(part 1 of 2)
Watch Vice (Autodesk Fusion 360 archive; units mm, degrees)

design "Watch Vice" references "WatchCase V3"
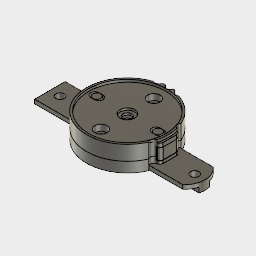
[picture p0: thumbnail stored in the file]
parameter "d90" = 4
parameter "d106" = 4
component_insert "Component Insert"
sketch "Sketch1"
  line L1 (0, 20.2285) -> (0, 20.1)
  line L2 (0, 20.95) -> (0, 20.2285)
  arc A1 centre (0, 0) radius 20.1 clockwise from (19.4682, -5) to (-3.612, 19.7728)
  arc A2 centre (19.1697, -3.3264) radius 1.7 clockwise from (20.869, -3.3751) to (19.4682, -5)
  arc A3 centre (-96.8326, 0) radius 117.75 clockwise from (20.869, 3.3751) to (20.869, -3.3751)
  arc A4 centre (19.1697, 3.3264) radius 1.7 clockwise from (19.4682, 5) to (20.869, 3.3751)
  arc A5 centre (0, 0) radius 20.1 clockwise from (3.612, 19.7728) to (19.4682, 5)
  arc A6 centre (2.1023, 18.9913) radius 1.7 clockwise from (0.8, 20.0841) to (3.612, 19.7728)
  arc A7 centre (0, 0) radius 20.1 clockwise from (-0.8, 20.0841) to (0.8, 20.0841)
  arc A8 centre (-2.1023, 18.9913) radius 1.7 clockwise from (-3.612, 19.7728) to (-0.8, 20.0841)
  arc A9 centre (0, 0) radius 21.6 clockwise from (-17.2241, -13.0342) to (-17.2241, 13.0342)
  arc A10 centre (-18.5, 13.9997) radius 1.6 clockwise from (-16.9962, 14.5462) to (-17.2241, 13.0342)
  arc A11 centre (-15.2104, 15.1952) radius 1.9 clockwise from (-16.9962, 14.5462) to (-14.5633, 16.9815)
  arc A12 centre (-14.0183, 18.4859) radius 1.6 clockwise from (-13.0515, 17.211) to (-14.5633, 16.9815)
  arc A13 centre (0, 0) radius 21.6 clockwise from (-13.0515, 17.211) to (13.0515, 17.211)
  arc A14 centre (14.0183, 18.4859) radius 1.6 clockwise from (14.5633, 16.9815) to (13.0515, 17.211)
  arc A15 centre (15.2104, 15.1952) radius 1.9 clockwise from (14.5633, 16.9815) to (16.9962, 14.5462)
  arc A16 centre (18.5, 13.9997) radius 1.6 clockwise from (17.2241, 13.0342) to (16.9962, 14.5462)
  arc A17 centre (0, 0) radius 21.6 clockwise from (17.2241, 13.0342) to (17.2241, -13.0342)
  arc A18 centre (18.5, -13.9997) radius 1.6 clockwise from (16.9962, -14.5462) to (17.2241, -13.0342)
  arc A19 centre (15.2104, -15.1952) radius 1.9 clockwise from (16.9962, -14.5462) to (14.5633, -16.9815)
  arc A20 centre (14.0183, -18.4859) radius 1.6 clockwise from (13.0515, -17.211) to (14.5633, -16.9815)
  arc A21 centre (0, 0) radius 21.6 clockwise from (13.0515, -17.211) to (-13.0515, -17.211)
  arc A22 centre (-14.0183, -18.4859) radius 1.6 clockwise from (-14.5633, -16.9815) to (-13.0515, -17.211)
  arc A23 centre (-15.2104, -15.1952) radius 1.9 clockwise from (-14.5633, -16.9815) to (-16.9962, -14.5462)
  arc A24 centre (-18.5, -13.9997) radius 1.6 clockwise from (-17.2241, -13.0342) to (-16.9962, -14.5462)
  circle C1 centre (15.2104, 15.1952) radius 0.625
  circle C2 centre (-15.2104, 15.1952) radius 0.625
  circle C3 centre (15.2104, -15.1952) radius 0.625
  circle C4 centre (-15.2104, -15.1952) radius 0.625
  circle C5 centre (5.1662, 20.5772) radius 1.75
  circle C6 centre (-5.1662, 20.5772) radius 1.75
  circle C7 centre (19.7754, 6.7228) radius 1.75
  circle C8 centre (19.7754, -6.7228) radius 1.75
  circle C9 centre (0, 20.1) radius 0.9
  circle C10 centre (0, 20.95) radius 1.75
  arc A25 centre (0, 0) radius 20.1 clockwise from (19.4682, 5) to (19.4682, -5)
  dimension "d6" diameter C8 = 3.5
  dimension "d7" diameter C9 = 1.8
  dimension "d8" diameter C10 = 3.5
extrude "Extrude1" new body sketch "Sketch1" profile of A1 A2 A3 A4 A5 A6 A7 A8 C5 C6 C7 C8 C10 blind 10
extrude "Extrude2" cut sketch "Sketch1" profile of A6 A7 A8 C10 no distance stored
extrude "Extrude3" sketch "Sketch1" profile of A2 A3 A4 A25 blind -1.1
offset_faces "OffsetFaces1" distance -0.1
sketch "Sketch2" plane through (0, 0, 0) normal (1, 0, 0) x axis (0, 1, 0)
  line L1 (-20, 10) -> (19.1, 10)
  line L2 (0, 3) -> (0, 0)
  line L3 (20, 3) -> (-20, 3)
  line L4 (0, 10) -> (0, 3)
  line L5 (-20, 3) -> (-20, 10)
  line L6 (-16, 6) -> (-16, 10)
  line L7 (-14.55, 6) -> (-16, 6)
  line L8 (-14.55, 3) -> (-14.55, 6)
  line L9 (-11.45, 6) -> (-11.45, 3)
  line L10 (-10, 6) -> (-11.45, 6)
  line L11 (-10, 10) -> (-10, 6)
  line L12 (11.45, 6) -> (11.45, 3)
  line L13 (10, 6) -> (11.45, 6)
  line L14 (10, 10) -> (10, 6)
  line L15 (-11.45, 6) -> (-14.55, 6)
  line L16 (-13, 10) -> (-13, 6)
  line L17 (-13, 3) -> (-13, 6)
  line L18 (13, 10) -> (13, 6)
  line L19 (13, 3) -> (13, 6)
  line L20 (-20, 0) -> (19.0241, 0)
  line L21 (-14.25, 0) -> (-14.25, 3)
  line L22 (-13, 0) -> (-13, 3)
  line L23 (-11.75, 0) -> (-11.75, 3)
  line L24 (-11.75, 3) -> (-14.25, 3)
  line L25 (13, 0) -> (13, 3)
  line L26 (11.75, 0) -> (11.75, 3)
  point P10 (-16, 10)
  point P11 (-16, 6)
  point P1 (0, 0)
  dimension "d19" distance P10 P11 = 4
  dimension "d20" distance L8 L9 = 3.1
  dimension "d22" distance L4 L11 = 10
  dimension "d23" distance L6 L11 = 6
  dimension "d24" distance P1 L3 = 3
  dimension "d27" distance L21 L23 = 2.5
  dimension "d28" distance L7 L20 = 6
revolve "Revolve1" sketch "Sketch2" AlongAngle 360
revolve "Revolve2" sketch "Sketch2" AlongAngle 360
work_plane "WorkPlane1" AlongDistance 3
split "Split1" bodies "Clamp Upper"
sketch "Sketch4" plane through (0, 0, 0) normal (0, 1, 0) x axis (1, 0, 0)
  line L1 (-20, 0) -> (20.8174, 0)
  line L2 (20.8174, 4) -> (20.8174, 0)
  line L3 (-20, 4) -> (20.8174, 4)
  line L4 (-20, 0) -> (-20, 4)
  point P4 (20.8174, 0)
  point P5 (20.8174, 4)
  dimension "d41" distance P4 P5 = 4
extrude "Extrude5" add sketch "Sketch4" distance 5.2
delete_face "DeleteFace1"
sketch "Sketch7" plane through (0, 0, 0) normal (0, 0, -1) x axis (1, 0, 0)
  line L1 (20.7887, 2.6) -> (-19.8303, 2.6)
  line L2 (38, 7.5) -> (-38, 7.5)
  line L3 (38, -7.5) -> (38, 7.5)
  line L4 (-38, -7.5) -> (38, -7.5)
  line L5 (-38, 7.5) -> (-38, -7.5)
  line L6 (-19.8303, -2.6) -> (20.7887, -2.6)
  line L7 (-20, 0) -> (-38, 0)
  line L8 (-34.6144, -7.5) -> (-34.6144, 7.5)
  line L9 (0, 7.5) -> (0, 0)
  line L10 (-38, 2.6) -> (-19.8303, 2.6)
  line L11 (-38, -2.6) -> (-19.8303, -2.6)
  line L12 (38, 2.6) -> (20.7887, 2.6)
  line L13 (38, -2.6) -> (20.7887, -2.6)
  arc A1 centre (-96.8326, 0) radius 117.65 clockwise from (20.7691, 3.3723) to (20.7887, 2.6)
  arc A2 centre (19.1697, 3.3264) radius 1.6 clockwise from (19.4506, 4.9016) to (20.7691, 3.3723)
  arc A3 centre (19.7754, 6.7228) radius 1.85 clockwise from (19.4506, 4.9016) to (18.365, 7.92)
  arc A4 centre (0, 0) radius 20 clockwise from (-19.8303, 2.6) to (18.365, 7.92)
  circle C1 centre (0, 13) radius 1.25
  arc A5 centre (0, 0) radius 20 clockwise from (-19.8303, -2.6) to (-19.8303, 2.6)
  circle C2 centre (-33, 0) radius 2.025
  arc A6 centre (-28, 0) radius 10 clockwise from (-34.6144, -7.5) to (-34.6144, 7.5)
  arc A7 centre (28, 0) radius 10 clockwise from (34.6144, 7.5) to (34.6144, -7.5)
  circle C3 centre (33, 0) radius 2.025
  arc A8 centre (5.1662, -20.5772) radius 1.85 clockwise from (3.5232, -19.7268) to (6.1713, -19.0241)
  arc A9 centre (0, 0) radius 20 clockwise from (18.365, -7.92) to (6.1713, -19.0241)
  arc A10 centre (19.7754, -6.7228) radius 1.85 clockwise from (18.365, -7.92) to (19.4506, -4.9016)
  arc A11 centre (19.1697, -3.3264) radius 1.6 clockwise from (20.7691, -3.3723) to (19.4506, -4.9016)
  arc A12 centre (-96.8326, 0) radius 117.65 clockwise from (20.7691, 3.3723) to (20.7691, -3.3723)
  arc A13 centre (19.1697, 3.3264) radius 1.6 clockwise from (19.4506, 4.9016) to (20.7691, 3.3723)
  arc A14 centre (19.7754, 6.7228) radius 1.85 clockwise from (19.4506, 4.9016) to (18.365, 7.92)
  arc A15 centre (0, 0) radius 20 clockwise from (-6.1713, -19.0241) to (18.365, 7.92)
  arc A16 centre (-5.1662, -20.5772) radius 1.85 clockwise from (-6.1713, -19.0241) to (-3.5232, -19.7268)
  arc A17 centre (-2.1023, -18.9913) radius 1.6 clockwise from (-1.8093, -20.5643) to (-3.5232, -19.7268)
  arc A18 centre (0, -20.95) radius 1.85 clockwise from (-1.8093, -20.5643) to (1.8093, -20.5643)
  arc A19 centre (2.1023, -18.9913) radius 1.6 clockwise from (3.5232, -19.7268) to (1.8093, -20.5643)
  circle C4 centre (0, 13) radius 1.55
  circle C5 centre (0, -13) radius 1.55
  point P12 (-38, 7.5)
  point P15 (-38, -7.5)
  point P1 (0, 0)
  point P23 (-33, 0)
  dimension "d73" distance P12 P15 = 15
  dimension "d74" distance P1 P23 = 33
  dimension "d76" radius A6 = 10
  dimension "d77" distance L5 P23 = 5
  dimension "d78" diameter C2 = 4.05
  dimension "d138" distance L10 L11 = 5.2
extrude "Extrude14" add sketch "Sketch7" profile of L1 A1 A2 A3 A4 L2 L4 L5 L6 A5 C2 A6 A7 C3 L10 L11 L12 L13 A8 A9 A10 A11 A12 A13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 along normal blind 2
offset_faces "OffsetFaces3" distance 2
extrude "Extrude15" add sketch "Sketch7" profile of L1 L6 A5 C2 A6 A7 C3 L10 L11 L12 L13 A12 A15 along normal blind 4.5
sketch "Sketch3" plane through (0, 0, 0) normal (0, 1, 0) x axis (1, 0, 0)
  line L1 (20, -10) -> (-20, -10)
  line L2 (0, -7) -> (0, 0)
  line L3 (3.6, -8) -> (3.6, -10)
  line L4 (2.1, -8) -> (3.6, -8)
  line L5 (2.1, -7) -> (2.1, -8)
  line L6 (0, -7) -> (2.1, -7)
  line L7 (0, -10) -> (0, -7)
  line L8 (3.6, -10) -> (0, -10)
  line L9 (20.8174, -3) -> (-20, -3)
  line L10 (-22, -7) -> (22, -7)
  line L11 (-22, -1.4022) -> (-22, -7)
  line L12 (22, -1.4022) -> (-22, -1.4022)
  line L13 (22, -7) -> (22, -1.4022)
  point P5 (3.6, -10)
  point P10 (0, -10)
  point P6 (3.6, -8)
  point P3 (20, -10)
  point P2 (-20, -10)
  point P8 (2.1, -7)
  dimension "d29" distance L5 L7 = 2.1
  dimension "d30" distance P5 P10 = 3.6
  dimension "d31" distance P5 P6 = 2
  dimension "d34" = 1
  dimension "d35" distance P3 L13 = 2
  dimension "d36" distance P2 L11 = 2
  dimension "d136" distance P5 P8 = 3
revolve "Revolve3" sketch "Sketch3" AlongAngle 360
extrude "Extrude4" cut sketch "Sketch3" profile of L6 L10 L11 L12 L13 distance 10
extrude "Extrude6" new body of existing geometry blind 5.6 bodies "Clamp Jaw 1"
offset_faces "OffsetFaces2" distance -0.15
sketch "Sketch5" plane through (0, 0, 0) normal (0, 1, 0) x axis (1, 0, 0)
  line L1 (20.8174, -7.0022) -> (-20, -7.0022)
  line L2 (-20, -1.5522) -> (20.8174, -1.5522)
  line L3 (6.8325, -1.5522) -> (4.8489, -7.0022)
  line L4 (0, -1.5522) -> (0, 0)
  line L5 (0, -7.0022) -> (0, -1.5522)
  line L6 (6.6197, -1.5522) -> (4.636, -7.0022)
  line L7 (0, -6.0022) -> (5, -6.0022)
  line L8 (-6.8325, -1.5522) -> (-4.8489, -7.0022)
  line L9 (-6.6197, -1.5522) -> (-4.636, -7.0022)
  line L10 (0, -6.0022) -> (-5, -6.0022)
  point P13 (5, -6.0022)
  point P14 (0, -6.0022)
  dimension "d47" distance L3 L6 = 0.2
  dimension "d48" angle L2 L6 = 70
  dimension "d49" distance P13 P14 = 5
  dimension "d50" distance L1 L7 = 1
extrude "Extrude7" cut sketch "Sketch5" profile of L1 L2 L3 L5 L6 L7 L8 L9 L10 distance 10 bodies "Clamp Jaw Center", "Clamp Jaws 2"
sketch "Sketch6" plane through (0, 0, 7.0022) normal (0, 0, 1) x axis (-1, 0, 0)
  line L1 (-4.8489, 4.85) -> (-4.8489, -4.85)
  line L2 (-19.0736, 4.85) -> (-4.8489, 4.85)
  line L3 (-4.8489, -4.85) -> (-19.0736, -4.85)
  line L4 (14, -2) -> (16, -2)
  line L5 (16, 2) -> (14, 2)
  line L6 (6.6197, -4.85) -> (-6.6197, -4.85)
  line L7 (0, -4.85) -> (0, 0)
  line L8 (0, 0) -> (14, 0)
  line L9 (16, 0) -> (14, 0)
  line L10 (-14, -2) -> (-16, -2)
  line L11 (-16, 2) -> (-14, 2)
  line L12 (1.7, -4) -> (1.7, -5.95)
  line L13 (-1.7, -4) -> (1.7, -4)
  line L14 (-1.7, -5.95) -> (-1.7, -4)
  line L15 (-1.9, -3.8) -> (1.9, -3.8)
  line L16 (-1.9, -5.95) -> (-1.9, -3.8)
  line L17 (1.9, -3.8) -> (1.9, -5.95)
  line L18 (1.7, 4) -> (1.7, 5.95)
  line L19 (1.9, 3.8) -> (1.9, 5.95)
  line L20 (-1.9, 5.95) -> (-1.9, 3.8)
  line L21 (-1.7, 5.95) -> (-1.7, 4)
  line L22 (-1.7, 4) -> (1.7, 4)
  line L23 (-1.9, 3.8) -> (1.9, 3.8)
  arc A1 centre (-19.174, 3.1734) radius 1.6 clockwise from (-20.7734, 3.2172) to (-19.4413, 4.7509)
  arc A2 centre (96.8326, 0) radius 117.65 clockwise from (-20.7734, -3.2172) to (-20.7734, 3.2172)
  arc A3 centre (-19.174, -3.1734) radius 1.6 clockwise from (-19.4413, -4.7509) to (-20.7734, -3.2172)
  arc A4 centre (14, 0) radius 2 clockwise from (14, -2) to (14, 2)
  arc A5 centre (16, 0) radius 2 clockwise from (16, 2) to (16, -2)
  circle C1 centre (15, 0) radius 1.95
  arc A6 centre (-14, 0) radius 2 clockwise from (-14, 2) to (-14, -2)
  arc A7 centre (-16, 0) radius 2 clockwise from (-16, -2) to (-16, 2)
  circle C2 centre (-15, 0) radius 1.95
  circle C3 centre (0, 0) radius 1.75
  arc A8 centre (0, -5.95) radius 1.7 clockwise from (1.7, -5.95) to (-1.7, -5.95)
  arc A9 centre (0, -5.95) radius 1.9 clockwise from (1.9, -5.95) to (-1.9, -5.95)
  arc A10 centre (0, 5.95) radius 1.7 clockwise from (-1.7, 5.95) to (1.7, 5.95)
  arc A11 centre (0, 5.95) radius 1.9 clockwise from (-1.9, 5.95) to (1.9, 5.95)
  arc A12 centre (-19.7754, 6.7228) radius 2 clockwise from (-19.0736, 4.85) to (-19.4413, 4.7509)
  arc A13 centre (-19.7754, -6.7228) radius 2 clockwise from (-19.4413, -4.7509) to (-19.0736, -4.85)
  point P13 (14, -2)
  point P16 (16, -2)
  point P1 (0, 0)
  point P21 (15, 0)
  point P32 (1.7, -5.95)
  dimension "d53" diameter A5 = 4
  dimension "d54" diameter C1 = 3.9 (= "d53 - 0.1 mm")
  dimension "d55" distance P13 P16 = 2
  dimension "d56" distance P1 P21 = 15
  dimension "d61" diameter C3 = 3.5
  dimension "d63" radius A8 = 1.7 (= "( 3.6 / 2 ) * 1 mm - 0.1 mm")
  dimension "d64" distance L6 P32 = 1.1
  dimension "d65" distance L8 L13 = 4
  dimension "d66" = 0.2
extrude "Extrude8" add sketch "Sketch6" profile of C1 C2 along normal blind 2
extrude "Extrude9" cut sketch "Sketch6" profile of A5 A4 L4 L5 C1 A6 L10 A7 C2 L11 along normal blind 7 and against normal blind 1
extrude "Extrude13" cut sketch "Sketch6" profile of C3 no distance stored
extrude "Extrude11" sketch "Sketch6" profile of L6 A8 L12 L14 A10 L18 L21 L22 to an object
extrude "Extrude16" cut sketch "Sketch6" profile of L6 A8 L12 L13 L14 L16 L15 L17 A9 A10 A11 L18 L19 L20 L21 L22 L23 to an object
sketch "Sketch13" plane through (0, 0, 10) normal (0, 0, 1) x axis (-1, 0, 0)
  circle C1 centre (0, 0) radius 19
  dimension "d133" diameter C1 = 38
extrude "Extrude21" cut sketch "Sketch13" against normal blind 1
extrude "Extrude22" add of existing geometry blind 0.2
sketch "Sketch8" plane through (0, 0, 0) normal (0, 0, 1) x axis (-1, 0, 0)
  line L1 (38, -7.5) -> (18.5405, -7.5)
  line L2 (38, 7.5) -> (38, -7.5)
  line L3 (18.5405, 7.5) -> (38, 7.5)
  line L4 (27, -7.5) -> (27, -13.5)
  line L5 (25, -7.5) -> (27, -7.5)
  line L6 (25, -13.5) -> (25, -7.5)
  line L7 (27, -13.5) -> (25, -13.5)
  line L8 (33, 0) -> (0, 0)
  line L9 (0, -19.1) -> (0, 0)
  line L10 (38, -7.5) -> (18.5405, -7.5)
  line L11 (38, 7.5) -> (38, -7.5)
  line L12 (18.5405, 7.5) -> (38, 7.5)
  line L13 (-18.0966, -7.5) -> (-34.6144, -7.5)
  line L14 (-34.6144, 7.5) -> (-18.0966, 7.5)
  line L15 (-25, -13.5) -> (-25, -7.5)
  line L16 (-27, -13.5) -> (-25, -13.5)
  line L17 (-27, -7.5) -> (-27, -13.5)
  line L18 (-25, -7.5) -> (-27, -7.5)
  line L19 (27, 7.5) -> (27, 13.5)
  line L20 (27, 13.5) -> (25, 13.5)
  line L21 (25, 13.5) -> (25, 7.5)
  line L22 (25, 7.5) -> (27, 7.5)
  line L23 (-27, 13.5) -> (-25, 13.5)
  line L24 (-27, 7.5) -> (-27, 13.5)
  line L25 (-25, 13.5) -> (-25, 7.5)
  line L26 (-25, 7.5) -> (-27, 7.5)
  line L27 (42.5, -12) -> (21.36, -12)
  line L28 (42.5, 3) -> (42.5, -12)
  line L29 (24.3156, 3) -> (42.5, 3)
  line L30 (-36.1394, 12) -> (-21.36, 12)
  line L31 (-21.36, -12) -> (-36.1394, -12)
  line L32 (38, -7.5) -> (18.5405, -7.5)
  line L33 (38, 7.5) -> (38, -7.5)
  line L34 (18.5405, 7.5) -> (38, 7.5)
  circle C1 centre (33, 0) radius 2.025
  arc A1 centre (0, 0) radius 20 clockwise from (18.5405, 7.5) to (18.5405, -7.5)
  arc A2 centre (0, -20.95) radius 1.85 clockwise from (-1.8093, -20.5643) to (1.8093, -20.5643)
  arc A3 centre (0, 0) radius 20 clockwise from (-18.365, 7.92) to (19.3649, 5)
  arc A4 centre (0, 0) radius 20 clockwise from (19.3649, -5) to (6.1713, -19.0241)
  arc A5 centre (5.1662, -20.5772) radius 1.85 clockwise from (3.5232, -19.7268) to (6.1713, -19.0241)
  arc A6 centre (2.1023, -18.9913) radius 1.6 clockwise from (3.5232, -19.7268) to (1.8093, -20.5643)
  arc A7 centre (0, -20.95) radius 1.85 clockwise from (-1.8093, -20.5643) to (1.8093, -20.5643)
  arc A8 centre (-2.1023, -18.9913) radius 1.6 clockwise from (-1.8093, -20.5643) to (-3.5232, -19.7268)
  arc A9 centre (-5.1662, -20.5772) radius 1.85 clockwise from (-6.1713, -19.0241) to (-3.5232, -19.7268)
  arc A10 centre (0, 0) radius 20 clockwise from (-6.1713, -19.0241) to (-18.365, -7.92)
  arc A11 centre (-28, 0) radius 10 clockwise from (-34.6144, -7.5) to (-34.6144, 7.5)
  arc A12 centre (0, 0) radius 24.5 clockwise from (-7.5598, -23.3045) to (-21.36, -12)
  arc A13 centre (-6.1713, -19.0241) radius 4.5 clockwise from (-5.6365, -23.4922) to (-7.5598, -23.3045)
  arc A14 centre (-2.1023, -18.9913) radius 5.7226 clockwise from (-1.0546, -24.6172) to (-5.6365, -23.4922)
  arc A15 centre (-1.8093, -20.5643) radius 4.1226 clockwise from (-0.001, -24.2691) to (-1.0546, -24.6172)
  arc A16 centre (1.8093, -20.5643) radius 4.1235 clockwise from (1.0544, -24.6181) to (-0.001, -24.2691)
  arc A17 centre (2.1023, -18.9913) radius 5.7235 clockwise from (5.6377, -23.4923) to (1.0544, -24.6181)
  arc A18 centre (6.1713, -19.0241) radius 4.5 clockwise from (7.5598, -23.3045) to (5.6377, -23.4923)
  arc A19 centre (0, 0) radius 24.5 clockwise from (21.36, -12) to (7.5598, -23.3045)
  arc A20 centre (-28, 0) radius 14.5 clockwise from (-36.1394, -12) to (-36.1394, 12)
  arc A21 centre (0, 0) radius 24.5 clockwise from (-21.36, 12) to (24.3156, 3)
  circle C2 centre (33, 0) radius 2.025
  arc A22 centre (0, 0) radius 20 clockwise from (18.5405, 7.5) to (18.5405, -7.5)
  point P8 (27, -13.5)
  point P11 (25, -13.5)
  point P10 (25, -7.5)
  dimension "d86" distance P8 P11 = 2
  dimension "d88" distance P10 P11 = 6
  dimension "d89" distance L6 L9 = 25
  dimension "d96" distance L2 L28 = 4.5
  dimension "d97" distance L1 L27 = 4.5 (= "d96")
  dimension "d98" distance L3 L29 = 4.5 (= "d96")
  dimension "d99" distance A3 A21 = 4.5 (= "d96")
  dimension "d100" distance A4 A19 = 4.5 (= "d96")
  dimension "d101" distance A10 A12 = 4.5 (= "d96")
  dimension "d102" distance L13 L31 = 4.5 (= "d96")
  dimension "d103" distance A11 A20 = 4.5 (= "d96")
  dimension "d104" distance L14 L30 = 4.5 (= "d96")
extrude "Extrude17" add sketch "Sketch8" profile of L4 L5 L6 L7 L10 L12 L13 L14 L15 L16 L17 L18 L19 L20 L21 L22 L23 L24 L25 L26 L27 L30 L31 L32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 against normal blind 1.5
mesh "Mesh2"
sketch "Sketch9" plane through (0, 0, 10.2) normal (0, 0, 1) x axis (-1, 0, 0)
  line L1 (18.1981, -17.1374) -> (17.1374, -18.1981)
  line L2 (14.6625, -13.6019) -> (18.1981, -17.1374)
  line L3 (13.6019, -14.6625) -> (14.6625, -13.6019)
  line L4 (17.1374, -18.1981) -> (13.6019, -14.6625)
  line L5 (0, -13) -> (0, 0)
  line L6 (0, 0) -> (14, 0)
  line L7 (0, 0) -> (14.1322, -14.1322)
  line L8 (-17.1374, -18.1981) -> (-13.6019, -14.6625)
  line L9 (-13.6019, -14.6625) -> (-14.6625, -13.6019)
  line L10 (-14.6625, -13.6019) -> (-18.1981, -17.1374)
  line L11 (-18.1981, -17.1374) -> (-17.1374, -18.1981)
  line L12 (17.1374, 18.1981) -> (13.6019, 14.6625)
  line L13 (13.6019, 14.6625) -> (14.6625, 13.6019)
  line L14 (14.6625, 13.6019) -> (18.1981, 17.1374)
  line L15 (18.1981, 17.1374) -> (17.1374, 18.1981)
  line L16 (-18.1981, 17.1374) -> (-17.1374, 18.1981)
  line L17 (-14.6625, 13.6019) -> (-18.1981, 17.1374)
  line L18 (-17.1374, 18.1981) -> (-13.6019, 14.6625)
  line L19 (-13.6019, 14.6625) -> (-14.6625, 13.6019)
  line L20 (1.9, 5) -> (19.3649, 5)
  line L21 (1.9, 5.95) -> (1.9, 5)
  line L22 (-1.9, 5) -> (-1.9, 5.95)
  line L23 (-19.1013, 5) -> (-1.9, 5)
  line L24 (-19.1013, -5) -> (-1.9, -5)
  line L25 (-1.9, -5.95) -> (-1.9, -5)
  line L26 (1.9, -5) -> (1.9, -5.95)
  line L27 (19.3649, -5) -> (1.9, -5)
  line L28 (3.756, 7) -> (20.8567, 7)
  line L29 (-19.1013, 7) -> (-3.756, 7)
  line L30 (-19.1013, -7) -> (-3.756, -7)
  line L31 (20.8567, -7) -> (3.756, -7)
  arc A1 centre (-19.7754, -6.7228) radius 1.85 clockwise from (-19.3869, -4.9141) to (-18.365, -7.92)
  arc A2 centre (-5.1662, -20.5772) radius 1.85 clockwise from (-6.1713, -19.0241) to (-3.5232, -19.7268)
  arc A3 centre (-2.1023, -18.9913) radius 1.6 clockwise from (-1.8093, -20.5643) to (-3.5232, -19.7268)
  arc A4 centre (0, -20.95) radius 1.85 clockwise from (-1.8093, -20.5643) to (1.8093, -20.5643)
  arc A5 centre (2.1023, -18.9913) radius 1.6 clockwise from (3.5232, -19.7268) to (1.8093, -20.5643)
  arc A6 centre (5.1662, -20.5772) radius 1.85 clockwise from (3.5232, -19.7268) to (6.1713, -19.0241)
  arc A7 centre (-19.7754, 6.7228) radius 1.85 clockwise from (-18.365, 7.92) to (-19.3869, 4.9141)
  arc A8 centre (-18.365, 7.92) radius 4 clockwise from (-22.365, 7.9253) to (-22.038, 9.504)
  arc A9 centre (0, 0) radius 24 clockwise from (-22.038, 9.504) to (7.4055, -22.8289)
  arc A10 centre (6.1713, -19.0241) radius 4 clockwise from (7.4055, -22.8289) to (5.9919, -23.0201)
  arc A11 centre (2.1023, -18.9913) radius 5.6 clockwise from (5.9919, -23.0201) to (1.077, -24.4967)
  arc A12 centre (1.8093, -20.5643) radius 4 clockwise from (1.077, -24.4967) to (0, -24.1317)
  arc A13 centre (-1.8093, -20.5643) radius 4 clockwise from (0, -24.1317) to (-1.077, -24.4967)
  arc A14 centre (-2.1023, -18.9913) radius 5.6 clockwise from (-1.077, -24.4967) to (-5.9919, -23.0201)
  arc A15 centre (-6.1713, -19.0241) radius 4 clockwise from (-5.9919, -23.0201) to (-7.4055, -22.8289)
  arc A16 centre (0, 0) radius 24 clockwise from (-7.4055, -22.8289) to (-22.038, -9.504)
  arc A17 centre (-18.365, -7.92) radius 4 clockwise from (-22.038, -9.504) to (-22.365, -7.9253)
  arc A18 centre (-19.7754, 6.7228) radius 1.85 clockwise from (-19.3869, 4.9141) to (-19.4506, 4.9016)
  arc A19 centre (-19.1697, 3.3264) radius 1.6 clockwise from (-20.7691, 3.3723) to (-19.4506, 4.9016)
  arc A20 centre (96.8326, 0) radius 117.65 clockwise from (-20.7691, -3.3723) to (-20.7691, 3.3723)
  arc A21 centre (-19.1697, -3.3264) radius 1.6 clockwise from (-19.4506, -4.9016) to (-20.7691, -3.3723)
  arc A22 centre (-19.7754, -6.7228) radius 1.85 clockwise from (-19.4506, -4.9016) to (-19.3869, -4.9141)
  arc A23 centre (-19.1697, -3.3264) radius 5.6 clockwise from (-22.365, -7.9253) to (-24.7674, -3.4869)
  arc A24 centre (96.8326, 0) radius 121.65 clockwise from (-24.7674, -3.4869) to (-24.7674, 3.4869)
  arc A25 centre (-19.1697, 3.3264) radius 5.6 clockwise from (-24.7674, 3.4869) to (-22.365, 7.9253)
  circle C1 centre (0, 0) radius 19
  arc A26 centre (0, 5.95) radius 1.9 clockwise from (-1.9, 5.95) to (1.9, 5.95)
  arc A27 centre (-19.7754, 6.7228) radius 1.85 clockwise from (-19.1013, 5) to (-19.4506, 4.9016)
  arc A28 centre (-19.1697, 3.3264) radius 1.6 clockwise from (-20.7691, 3.3723) to (-19.4506, 4.9016)
  arc A29 centre (96.8326, 0) radius 117.65 clockwise from (-20.7691, -3.3723) to (-20.7691, 3.3723)
  arc A30 centre (-19.7754, -6.7228) radius 1.85 clockwise from (-19.4506, -4.9016) to (-19.1013, -5)
  arc A31 centre (0, -5.95) radius 1.9 clockwise from (1.9, -5.95) to (-1.9, -5.95)
  arc A32 centre (0, 0) radius 20 clockwise from (19.3649, 5) to (19.3649, -5)
  arc A33 centre (-19.1697, -3.3264) radius 1.6 clockwise from (-19.4506, -4.9016) to (-20.7691, -3.3723)
  arc A34 centre (0, 5.95) radius 3.9 clockwise from (-3.756, 7) to (3.756, 7)
  arc A35 centre (-19.1013, 5) radius 2 clockwise from (-19.8162, 6.8679) to (-19.1013, 7)
  arc A36 centre (-19.1697, 3.3264) radius 3.6 clockwise from (-22.7682, 3.4296) to (-19.8162, 6.8679)
  arc A37 centre (96.8326, 0) radius 119.65 clockwise from (-22.7682, -3.4296) to (-22.7682, 3.4296)
  arc A38 centre (-19.1697, -3.3264) radius 3.6 clockwise from (-19.8162, -6.8679) to (-22.7682, -3.4296)
  arc A39 centre (-19.1013, -5) radius 2 clockwise from (-19.1013, -7) to (-19.8162, -6.8679)
  arc A40 centre (0, -5.95) radius 3.9 clockwise from (3.756, -7) to (-3.756, -7)
  arc A41 centre (0, 0) radius 22 clockwise from (20.8567, 7) to (20.8567, -7)
  circle C2 centre (0, 0) radius 19
  arc A42 centre (0, 0) radius 20 clockwise from (-19.3869, -4.9141) to (-19.3869, 4.9141)
  arc A43 centre (-19.7754, -6.7228) radius 1.85 clockwise from (-19.3869, -4.9141) to (-18.365, -7.92)
  arc A44 centre (0, 0) radius 20 clockwise from (-6.1713, -19.0241) to (-18.365, -7.92)
  arc A45 centre (-5.1662, -20.5772) radius 1.85 clockwise from (-6.1713, -19.0241) to (-3.5232, -19.7268)
  arc A46 centre (-2.1023, -18.9913) radius 1.6 clockwise from (-1.8093, -20.5643) to (-3.5232, -19.7268)
  arc A47 centre (0, -20.95) radius 1.85 clockwise from (-1.8093, -20.5643) to (1.8093, -20.5643)
  arc A48 centre (2.1023, -18.9913) radius 1.6 clockwise from (3.5232, -19.7268) to (1.8093, -20.5643)
  arc A49 centre (5.1662, -20.5772) radius 1.85 clockwise from (3.5232, -19.7268) to (6.1713, -19.0241)
  arc A50 centre (0, 0) radius 20 clockwise from (-18.365, 7.92) to (6.1713, -19.0241)
  arc A51 centre (-19.7754, 6.7228) radius 1.85 clockwise from (-18.365, 7.92) to (-19.3869, 4.9141)
  point P20 (17.1374, -18.1981)
  point P21 (18.1981, -17.1374)
  point P22 (14.6625, -13.6019)
  dimension "d107" angle L6 L7 = 45
  dimension "d108" distance P20 P21 = 1.5
  dimension "d109" distance P21 P22 = 5 (= "d106 + 1 mm")
  dimension "d137" = 2
extrude "Extrude18" add sketch "Sketch9" profile of L2 L3 L4 A9 A16 L8 L9 L10 L12 L13 L14 L17 L18 L19 A44 A50 blind 1 from offset -7
move "Move1"
move "Move2"
sketch "Sketch10"
  line L1 (-2.3489, -4.85) -> (-16.903, -4.85)
  line L2 (-16.903, 4.85) -> (-2.3489, 4.85)
  line L3 (-2.3489, 4.85) -> (-2.3489, -4.85)
  line L4 (2.3489, -4.85) -> (2.3489, 4.85)
  line L5 (16.5736, -4.85) -> (2.3489, -4.85)
  line L6 (2.3489, 4.85) -> (16.5736, 4.85)
  line L7 (-13.703, 10.35) -> (-14.903, 10.35)
  line L8 (-13.703, 4.85) -> (-13.703, 10.35)
  line L9 (-14.903, 4.85) -> (-13.703, 4.85)
  line L10 (-14.903, 10.35) -> (-14.903, 4.85)
  line L11 (-6.3325, 10.35) -> (-7.5325, 10.35)
  line L12 (-6.3325, 4.85) -> (-6.3325, 10.35)
  line L13 (-7.5325, 4.85) -> (-6.3325, 4.85)
  line L14 (-7.5325, 10.35) -> (-7.5325, 4.85)
  line L15 (-9.0259, -4.35) -> (-10.2259, -4.35)
  line L16 (-9.0259, -9.85) -> (-9.0259, -4.35)
  line L17 (-10.2259, -9.85) -> (-9.0259, -9.85)
  line L18 (-10.2259, -4.35) -> (-10.2259, -9.85)
  line L19 (-9.6259, -4.85) -> (-9.6259, -4.35)
  line L20 (0, 5.5144) -> (0, 0)
  line L21 (6.3325, 4.85) -> (6.3325, 10.35)
  line L22 (6.3325, 10.35) -> (7.5325, 10.35)
  line L23 (7.5325, 10.35) -> (7.5325, 4.85)
  line L24 (7.5325, 4.85) -> (6.3325, 4.85)
  line L25 (14.903, 4.85) -> (13.703, 4.85)
  line L26 (13.703, 4.85) -> (13.703, 10.35)
  line L27 (14.903, 10.35) -> (14.903, 4.85)
  line L28 (13.703, 10.35) -> (14.903, 10.35)
  line L29 (9.0259, -4.35) -> (10.2259, -4.35)
  line L30 (9.0259, -9.85) -> (9.0259, -4.35)
  line L31 (10.2259, -4.35) -> (10.2259, -9.85)
  line L32 (10.2259, -9.85) -> (9.0259, -9.85)
  line L33 (2.3489, -4.85) -> (-2.3489, -4.85)
  line L34 (2.3489, 4.85) -> (-2.3489, 4.85)
  line L35 (2.3489, 8.85) -> (-2.3489, 8.85)
  line L36 (2.3489, 8.85) -> (16.5736, 8.85)
  line L37 (16.5736, -8.85) -> (2.3489, -8.85)
  line L38 (2.3489, -8.85) -> (-2.3489, -8.85)
  line L39 (-2.3489, -8.85) -> (-19.8087, -8.85)
  line L40 (-19.8087, 8.85) -> (-2.3489, 8.85)
  line L41 (-4.3325, -4.85) -> (-4.3325, 4.85)
  line L42 (4.3325, 4.85) -> (4.3325, -4.85)
  line L43 (-2.3489, -4.85) -> (-4.3325, -4.85)
  line L44 (-4.3325, 4.85) -> (-2.3489, 4.85)
  line L45 (2.3489, 4.85) -> (4.3325, 4.85)
  line L46 (4.3325, -4.85) -> (2.3489, -4.85)
  arc A1 centre (2.5, 0) radius 20 clockwise from (-16.903, -4.85) to (-16.903, 4.85)
  arc A2 centre (-99.3326, 0) radius 117.65 clockwise from (18.2734, 3.2172) to (18.2734, -3.2172)
  arc A3 centre (17.2754, -6.7228) radius 2 clockwise from (16.5736, -4.85) to (16.9413, -4.7509)
  arc A4 centre (16.674, -3.1734) radius 1.6 clockwise from (18.2734, -3.2172) to (16.9413, -4.7509)
  arc A5 centre (16.674, 3.1734) radius 1.6 clockwise from (16.9413, 4.7509) to (18.2734, 3.2172)
  arc A6 centre (17.2754, 6.7228) radius 2 clockwise from (16.9413, 4.7509) to (16.5736, 4.85)
  arc A7 centre (16.5736, 4.85) radius 4 clockwise from (16.5736, 8.85) to (17.7855, 8.662)
  arc A8 centre (16.674, 3.1734) radius 5.6 clockwise from (17.7855, 8.662) to (22.2719, 3.3265)
  arc A9 centre (-99.3326, 0) radius 121.65 clockwise from (22.2719, 3.3265) to (22.2719, -3.3265)
  arc A10 centre (16.674, -3.1734) radius 5.6 clockwise from (22.2719, -3.3265) to (17.7855, -8.662)
  arc A11 centre (16.5736, -4.85) radius 4 clockwise from (17.7855, -8.662) to (16.5736, -8.85)
  arc A12 centre (2.5, 0) radius 24 clockwise from (-19.8087, -8.85) to (-19.8087, 8.85)
  point P4 (-16.903, 4.85)
  point P34 (-4.3325, 4.85)
  dimension "d118" distance L1 L15 = 0.5
  dimension "d119" distance L1 L17 = 5
  dimension "d121" distance L16 L18 = 1.2
  dimension "d122" distance P4 L10 = 2
  dimension "d123" distance L12 P34 = 2
  dimension "d127" = 4
extrude "Extrude19" sketch "Sketch10" profile of L1 L2 L5 L6 L7 L8 L9 L10 L11 L12 L13 L14 L16 L17 L18 L21 L22 L23 L24 L25 L26 L27 L28 L30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 blind 1
sketch "Sketch12" plane through (0, 0, 1.5522) normal (0, 0, -1) x axis (1, 0, 0)
  line L1 (-1.7, 4.85) -> (-6.6197, 4.85)
  line L2 (-1.7, 5.95) -> (-1.7, 4.85)
  line L3 (1.7, 4.85) -> (1.7, 5.95)
  line L4 (6.6197, 4.85) -> (1.7, 4.85)
  line L5 (6.6197, 4.85) -> (6.6197, -4.85)
  line L6 (1.7, -4.85) -> (6.6197, -4.85)
  line L7 (1.7, -5.95) -> (1.7, -4.85)
  line L8 (-1.7, -4.85) -> (-1.7, -5.95)
  line L9 (-6.6197, -4.85) -> (-1.7, -4.85)
  line L10 (-6.6197, -4.85) -> (-6.6197, 4.85)
  line L11 (-5.4479, 9.85) -> (-11.6197, 9.85)
  line L12 (-11.6197, -9.85) -> (-11.6197, 9.85)
  line L13 (-11.6197, -9.85) -> (-5.4479, -9.85)
  line L14 (5.4479, -9.85) -> (11.6197, -9.85)
  line L15 (11.6197, 9.85) -> (11.6197, -9.85)
  line L16 (11.6197, 9.85) -> (5.4479, 9.85)
  line L17 (-5.1197, 4.85) -> (-6.6197, 4.85)
  line L18 (-5.1197, 9.85) -> (-5.1197, 4.85)
  line L19 (-6.6197, 9.85) -> (-5.1197, 9.85)
  line L20 (-6.6197, 4.85) -> (-6.6197, 9.85)
  line L21 (5.1197, 4.85) -> (6.6197, 4.85)
  line L22 (5.1197, 9.85) -> (5.1197, 4.85)
  line L23 (6.6197, 9.85) -> (5.1197, 9.85)
  line L24 (6.6197, 4.85) -> (6.6197, 9.85)
  line L25 (-5.1197, -4.85) -> (-6.6197, -4.85)
  line L26 (-5.1197, -9.85) -> (-5.1197, -4.85)
  line L27 (-6.6197, -9.85) -> (-5.1197, -9.85)
  line L28 (-6.6197, -4.85) -> (-6.6197, -9.85)
  line L29 (5.1197, -4.85) -> (6.6197, -4.85)
  line L30 (5.1197, -9.85) -> (5.1197, -4.85)
  line L31 (6.6197, -9.85) -> (5.1197, -9.85)
  line L32 (6.6197, -4.85) -> (6.6197, -9.85)
  arc A1 centre (0, 5.95) radius 1.7 clockwise from (-1.7, 5.95) to (1.7, 5.95)
  arc A2 centre (0, -5.95) radius 1.7 clockwise from (1.7, -5.95) to (-1.7, -5.95)
  arc A3 centre (0, 5.95) radius 6.7 clockwise from (-5.4479, 9.85) to (5.4479, 9.85)
  arc A4 centre (0, -5.95) radius 6.7 clockwise from (5.4479, -9.85) to (-5.4479, -9.85)
  dimension "d129" = 5
  dimension "d130" distance L18 L20 = 1.5
extrude "Extrude20" add sketch "Sketch12" profile of L1 L4 L6 L9 L16 L14 L11 L13 L17 L18 L19 L20 L21 L22 L23 L24 L25 L26 L27 L28 L29 L30 L31 L32 against normal blind 1
delete_face "DeleteFace3"
delete_face "DeleteFace4"
named bodies: "Clamp Bottom", "Clamp Upper", "Clamp Jaw 1", "Clamp Jaw Center", "Clamp Jaws 2"

design "WatchCase V3" references "Watch Vice Fixture CAD"
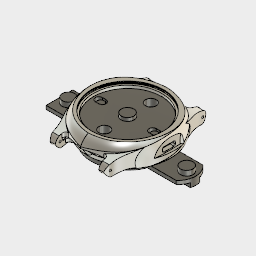
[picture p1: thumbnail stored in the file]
parameter "LugSpacing" = 24
parameter "d280" = 4
sketch "Sketch1"
  line L1 (8, 14) -> (-8, 14)
  line L2 (8, -14) -> (8, 14)
  line L3 (-8, -14) -> (8, -14)
  line L4 (-8, 14) -> (-8, -14)
  line L5 (0, 0) -> (0, 14)
  line L6 (8, 0) -> (0, 0)
  line L7 (0, 14) -> (0, 20.1)
  line L8 (18.5, 5.2) -> (15.5, 5.2)
  line L9 (18.5, -5.2) -> (18.5, 5.2)
  line L10 (15.5, -5.2) -> (18.5, -5.2)
  line L11 (15.5, 5.2) -> (15.5, -5.2)
  line L12 (8, 0) -> (15.5, 0)
  line L13 (19.5, 2.25) -> (18.5, 2.25)
  line L14 (19.5, -2.25) -> (19.5, 2.25)
  line L15 (18.5, -2.25) -> (19.5, -2.25)
  line L16 (19.5, 0.75) -> (18.5, 0.75)
  line L17 (19.5, -0.75) -> (18.5, -0.75)
  line L18 (19.5, 0.75) -> (19.5, -0.75)
  line L19 (18.5, 0) -> (19.5, 0)
  line L20 (-0.8, 20.0841) -> (-0.8, 19.9841)
  line L21 (0.8, 20.0841) -> (0.8, 19.9841)
  circle C1 centre (0, 0) radius 20.1
  circle C2 centre (0, 0) radius 18.85
  circle C3 centre (0, 0) radius 10
  arc A1 centre (0, 19.9841) radius 0.8 clockwise from (0.8, 19.9841) to (-0.8, 19.9841)
  point P4 (-8, 14)
  point P5 (8, 14)
  point P6 (8, -14)
  point P13 (15.5, 5.2)
  point P16 (15.5, -5.2)
  point P14 (18.5, 5.2)
  point P3 (0, 0)
  point P23 (19.5, 0.75)
  point P25 (19.5, -0.75)
  point P29 (0.8, 19.9841)
  point P32 (0.8, 20.0841)
  dimension "d1" diameter C1 = 40.2
  dimension "d3" distance C1 C2 = 1.25
  dimension "d4" diameter C3 = 20
  dimension "d5" distance P4 P5 = 16
  dimension "d6" distance P5 P6 = 28
  dimension "d22" distance P13 P16 = 10.4
  dimension "d23" distance P13 P14 = 3
  dimension "d24" distance P3 L9 = 18.5
  dimension "d25" distance P23 P25 = 1.5
  dimension "d26" distance L13 L16 = 1.5
  dimension "d45" distance P3 = 5.5
  dimension "d108" distance P3 = 1.5
  dimension "d262" distance P3 = 16.5
  dimension "d266" distance P3 = 22
  dimension "d312" radius A1 = 0.8
  dimension "d313" distance P29 P32 = 0.1
  dimension "d170" OffsetX = 0
  dimension "d171" OffsetY = 0
  dimension "d172" OffsetZ = 0
  dimension "d173" AngleZ = 0
  dimension "d194" OffsetX = 0
  dimension "d195" OffsetY = 0
  dimension "d196" OffsetZ = 0
  dimension "d197" AngleZ = 0
extrude "Extrude1" new body sketch "Sketch1" profile of C1 C2 L1 L2 L3 L4 C3 L8 L9 L10 L11 L13 L14 L15 L16 L17 L18 A1 L20 L21 blind 1.6 bodies "WatchBlank"
extrude "Extrude2" add sketch "Sketch1" profile of L1 L2 L3 L4 C3 blind -5.8
extrude "Extrude3" add sketch "Sketch1" profile of C2 L1 L2 L3 L4 C3 blind 3.1
work_plane "WorkPlane1" AlongDistance -14.2
sketch "Sketch2" plane through (-14.2, 0, 0) normal (1, 0, 0) x axis (0, 1, 0)
  line L1 (3.95, -3) -> (3.95, 0)
  line L2 (-3.95, -3) -> (3.95, -3)
  line L3 (-3.95, 0) -> (-3.95, -3)
  line L4 (3.95, 0) -> (-3.95, 0)
  line L5 (0, -3) -> (0, 0)
  line L6 (-20.1, 0) -> (20.1, 0)
  point P2 (3.95, 0)
  point P5 (-3.95, 0)
  point P4 (-3.95, -3)
  dimension "d18" distance P2 P5 = 7.9
  dimension "d19" distance P4 P5 = 3
extrude "Extrude4" add sketch "Sketch2" profile of L1 L2 L3 L4 L6 against normal blind 6.56
extrude "Extrude5" add sketch "Sketch1" profile of C2 L8 L9 L10 L11 blind -2
extrude "Extrude6" add sketch "Sketch1" profile of C2 L9 L14 L16 L17 L18 blind -1.75 second side blind 1.15 (= "1.75 mm - 0.6 mm")
work_plane "WorkPlane2"
sketch "Sketch3" plane through (0, 0, -1.35) normal (0, 0, 1) x axis (1, 0, 0)
  line L1 (0, -22) -> (0, 1)
  line L2 (0, 22) -> (0, 0)
  line L3 (22, 0) -> (0, 0)
  line L4 (0, 27.5) -> (0, 22)
  line L5
  curve K1 (0, 27.5) -> (0, -27.5)
  curve K2 (-6, 28) -> (6, 27)
  curve K3 (7.7672, -26.1119) -> (-7.7672, -28.8881)
  curve K4 (26, 9) -> (26, -5)
  circle C1 centre (0, 0) radius 19
  circle C2 centre (0, 0) radius 22
  circle C3 centre (0, 0) radius 32
  point P6 (0, -22)
  point P10 (0, -27.5)
  point P8 (0, 22)
  point P11 (0, 27.5)
  dimension "d33" diameter C1 = 38
  dimension "d34" distance C1 C2 = 3
  dimension "d44" distance C2 C3 = 10
  dimension "d45" distance P6 P10 = 5.5
  dimension "d46" distance P8 P11 = 5.5
sketch "Sketch8" plane through (0, 0, -1.35) normal (0, 0, 1) x axis (1, 0, 0)
  curve K1 (0, 27.5) -> (0, -27.5)
  line L1 (0, 27.5) -> (0, 22)
  curve K2 (-5.077, 27.7287) -> (5.077, 27.2713)
  curve K3 (7.4837, -26.6298) -> (-7.4837, -28.3702)
  curve K4 (26.5114, 8) -> (26.5114, -6)
sketch "Sketch6" plane through (0, 0, 0) normal (1, 0, 0) x axis (0, 1, 0)
  line L1 (-22, 4.15) -> (-22, -6.85)
  line L2 (-22, -6.85) -> (-27, -6.85)
  line L3 (-35, -6.85) -> (-27, -6.85)
  line L4 (-35, 4.15) -> (-35, -6.85)
  line L5 (-22, 4.15) -> (-35, 4.15)
  line L6 (22, -6.85) -> (22, 4.15)
  line L7 (35, -6.85) -> (22, -6.85)
  line L8 (35, 4.15) -> (35, -6.85)
  line L9 (22, 4.15) -> (35, 4.15)
  arc A1 centre (-17.2456, -4.6475) radius 10 clockwise from (-27, -6.85) to (-22, 4.15)
  arc A2 centre (15.8225, -0.8201) radius 10 clockwise from (24.5, 4.15) to (23.8, -6.85)
  arc A3 centre (3.71, -0.0109) radius 30 clockwise from (-25.5, -6.85) to (-26, 4.15)
  arc A4 centre (-2.256, -13.4898) radius 30 clockwise from (22.01, 4.15) to (27, -6.85)
  point P2 (-22, -6.85)
  point P3 (-22, 4.15)
  point P9 (-35, 4.15)
  point P15 (24.5, 4.15)
  point P16 (23.8, -6.85)
  point P10 (22, 4.15)
  point P21 (22.01, 4.15)
  point P11 (22, -6.85)
  point P22 (27, -6.85)
  point P19 (-25.5, -6.85)
  point P5 (-27, -6.85)
  point P7 (-22, -6.85)
  point P18 (-26, 4.15)
  dimension "d35" distance P2 P3 = 11
  dimension "d36" distance P3 P9 = 13
  dimension "d37" distance L6 P15 = 2.5
  dimension "d38" distance L6 P16 = 1.8
  dimension "d39" radius A2 = 10
  dimension "d47" radius A4 = 30
  dimension "d48" distance P10 P21 = 0.01
  dimension "d49" distance P11 P22 = 5
  dimension "d54" distance P2 P19 = 3.5
  dimension "d55" distance P5 P7 = 5
  dimension "d56" distance P3 P18 = 4
  dimension "d57" radius A3 = 30
  dimension "d68" radius A1 = 10
extrude "Extrude7" new body sketch "Sketch3" profile of C1 C2 C3 distance 11
loft "Loft1" sketch "Sketch6"
loft "Loft2" sketch "Sketch6"
mirror "Mirror1"
offset_faces "OffsetFaces1" distance -0.3
move "Move1"
combine "Combine1"
extrude "Extrude9" cut of existing geometry no distance stored
extrude "Extrude8" cut of existing geometry no distance stored
extrude "Extrude11" cut of existing geometry no distance stored
offset_faces "OffsetFaces3" distance 0.6
extrude "Extrude13" sketch "Sketch1" profile of C1 C2 L8 L9 L10 L13 L14 L15 L18 A1 L20 L21 blind 0 from offset 1.6
sketch "Sketch19" plane through (0, 0, -0.3) normal (0, 0, -1) x axis (1, 0, 0)
  line L1 (0.8, -19.9841) -> (0.8, -20.0841)
  line L2 (-0.8, -20.0841) -> (-0.8, -19.9841)
  line L3 (0, -18) -> (0, -19.1841)
  line L4 (-0.8, -20.0841) -> (-2.1023, -18.9913)
  arc A1 centre (0, -19.9841) radius 0.8 clockwise from (-0.8, -19.9841) to (0.8, -19.9841)
  arc A2 centre (0, 0) radius 20.1 clockwise from (0.8, -20.0841) to (-0.8, -20.0841)
  circle C1 centre (-2.1023, -18.9913) radius 1.7
  circle C2 centre (0, 0) radius 19
  circle C3 centre (2.1023, -18.9913) radius 1.7
  dimension "d322" diameter C1 = 3.4 (= "( 1.7 * 2 ) * 1 mm")
  dimension "d395" angle L3 L4 = 50
extrude "Extrude31" cut sketch "Sketch19" profile of L1 A1 L2 A2 C1 C2 C3 to an object Side2Offset 0
sketch "Sketch9" plane through (0, 0, 0) normal (1, 0, 0) x axis (0, 1, 0)
  line L1 (-9, 2.5959) -> (-9, -2.573)
  line L2 (-9, -4.4041) -> (-25.1866, -7.5504)
  line L3 (-9, -2.573) -> (-9, -4.4041)
  line L4 (-25.5, -4.2) -> (-25.7828, -4.4828)
  line L5 (-22.5, -7.0282) -> (-22.5, -4.2)
  line L6 (-28.5, -1.2) -> (-25.5, -1.2)
  line L7 (-28.5, -4.2) -> (-28.5, -1.2)
  line L8 (-24.3, -4.2) -> (-25.5, -4.2)
  line L9 (-20.2, 0.4492) -> (-20.2, -6.5811)
  line L10 (-21.5832, -6.85) -> (-22.5, -6.85)
  line L11 (-21.5, 0.103) -> (-22.5, -4.2)
  circle C1 centre (-25.7828, -4.4828) radius 0.625
  arc A1 centre (-25.7828, -4.4828) radius 3.125 clockwise from (-25.1866, -7.5504) to (-26.2156, -1.388)
  arc A2 centre (-17.2456, -4.6475) radius 10 clockwise from (-26.2877, -0.3767) to (-22, 4.15)
  arc A3 centre (-40.0649, 97.6484) radius 100 clockwise from (-9, 2.5959) to (-26.2156, -1.388)
  arc A4 centre (-23.4639, -5.5627) radius 5 clockwise from (-28.4301, -6.1435) to (-26.2156, -1.388)
  arc A5 centre (-22.6822, -2.0981) radius 6 clockwise from (-25.1866, -7.5504) to (-28.5947, -3.1193)
  circle C2 centre (-25.5, -4.2) radius 0.625
  circle C3 centre (-25.5, -4.2) radius 3
  arc A6 centre (2.3083, -86.6908) radius 90 clockwise from (-26.7933, -1.5257) to (-9, 2.5959)
  arc A7 centre (-23.4639, -5.5627) radius 5 clockwise from (-26.2156, -1.388) to (-26.02, -1.2654)
  point P1 (0, 0)
  point P9 (-9, 2.5959)
  point P12 (-9, -4.4041)
  point P13 (-28.4301, -6.1435)
  point P15 (-28.5947, -3.1193)
  point P18 (-25.7828, -4.4828)
  point P19 (-25.5, -4.2)
  point P17 (-25.5, -4.2)
  point P20 (-25.5, -4.2)
  point P22 (-22.5, -4.2)
  point P36 (-21.5, 0.103)
  dimension "d71" distance C1 A1 = 2.5
  dimension "d72" diameter C1 = 1.25
  dimension "d74" radius A3 = 100
  dimension "d75" distance P1 P9 = 9
  dimension "d77" angle L2 L3 = 101
  dimension "d78" distance P9 P12 = 7
  dimension "d84" radius A4 = 5
  dimension "d85" distance L2 P13 = 2
  dimension "d86" distance L2 P15 = 5
  dimension "d87" radius A5 = 6
  dimension "d248" diameter C2 = 1.25
  dimension "d249" distance P18 P19 = 0.4
  dimension "d250" distance P1 P17 = 4.2
  dimension "d251" diameter C3 = 6
  dimension "d291" distance P1 P20 = 25.5
  dimension "d293" angle L4 L8 = 45
  dimension "d296" radius A6 = 90
  dimension "d335" distance L5 L9 = 2.3
  dimension "d342" distance P22 P36 = 1
sketch "Sketch15"
  curve K1 (21, -10) -> (14.5, -29)
  curve K2 (16.9276, -20.523) -> (16.0724, -23.477)
  curve K3 (15.7524, -27.1106) -> (13.2476, -30.8894)
  curve K4 (21.5784, -7.8364) -> (20.4216, -12.1636)
  line L1 (12.1, -10) -> (21, -10)
  line L2 (12.1, -29) -> (12.1, -10)
  line L3 (12.1, -29) -> (14.5, -29)
  arc A1 centre (0, 0) radius 20.2 clockwise from (17.5511, -10) to (12.1, -16.175)
  point P1 (0, 0)
  point P3 (16.5, -22)
  point P2 (14.5, -29)
  point P13 (0, 0)
  point P4 (21, -10)
  dimension "d262" distance P1 P3 = 16.5
  dimension "d263" distance P2 P13 = 14.5
  dimension "d264" distance P1 P4 = 21
  dimension "d265" distance P1 P4 = 10
  dimension "d266" distance P1 P3 = 22
  dimension "d267" distance P1 P2 = 29
  dimension "d269" distance P1 L2 = 12.1 (= "( 24.2 / 2 ) * 1 mm")
  dimension "d295" radius A1 = 20.2
extrude "Extrude25" cut sketch "Sketch9" profile of A1 L2 A4 A5 C2 C3 L5 L6 L7 A6 A7 distance 20
extrude "Extrude14" new body sketch "Sketch9" profile of L1 L2 L3 A4 A5 C2 C3 L5 L6 A6 A7 along normal blind 0 and along normal blind 40 bodies "Lug1"
extrude "Extrude26" sketch "Sketch15" profile of K1 L1 L2 L3 blind 10 second side blind 10
work_plane "WorkPlane5" AlongDistance 0.25
mirror "Mirror10"
mirror "Mirror6" bodies "Lug2"
mirror "Mirror8" bodies "Lug3", "Lug4"
extrude "Extrude33" new body sketch "Sketch9" profile of L2 C3 L5 A6 L9 L10 L11 to an object Side2Offset 0
mirror "Mirror12"
chamfer "Chamfer4" distance 2.6
combine "Combine2" bodies "Lug1", "Lug2", "Lug4", "Lug3"
offset_faces "OffsetFaces2" distance 0.6665
fillet "Fillet30" radius 1.6
work_plane "WorkPlane7" AlongDistance 0
sketch "Sketch22" plane through (0, -22.5, 0) normal (0, -1, 0) x axis (1, 0, 0)
  line L1 (-9.6626, -9.5527) -> (-10.2743, -2.5603)
  line L2 (-12.1, -9.5527) -> (-9.6626, -9.5527)
  line L3 (-12.1, -4.5527) -> (-12.1, -9.5527)
  line L4 (-7.2621, -9.1294) -> (-9.6626, -9.5527)
  line L5 (-8.1304, -4.2054) -> (-7.2621, -9.1294)
  line L6 (-12.1, -3.575) -> (-12.1, -4.825)
  line L7 (-10.1, -4.5527) -> (-12.1, -4.2)
  line L8 (10.5, -4.2) -> (-10.5, -4.2)
  arc A1 centre (-10.1, -4.5527) radius 2 clockwise from (-12.1, -4.5527) to (-10.2743, -2.5603)
  arc A2 centre (-10.1, -4.5527) radius 2 clockwise from (-10.2743, -2.5603) to (-8.1304, -4.2054)
  point P4 (-12.1, -9.5527)
  point P5 (-12.1, -4.5527)
  dimension "d360" radius A1 = 2
  dimension "d400" distance P4 P5 = 5
  dimension "d401" angle L5 L8 = 80
  dimension "d411" angle L3 L7 = 80
revolve "Revolve1" sketch "Sketch22" AlongAngle 360
extrude "Extrude36" cut sketch "Sketch22" profile of L1 L2 L3 A1 A2 L4 L5 along normal blind 5
mirror "Mirror14"
work_plane "WorkPlane9"
sketch "Sketch24" plane through (0, 0, 0) normal (0.9096, -0.4154, 0) x axis (0.4154, 0.9096, 0)
  line L1 (-25.1899, -4.2146) -> (-25.1899, -2.2146)
  line L2 (-27.1899, -9.5589) -> (-27.1899, -2.5589)
  line L3 (-22.3908, -9.5589) -> (-27.1899, -9.5589)
  curve K1 (-22.3908, -6.85) -> (-22.6825, -4.3183)
  line L4 (-24.6624, -2.5589) -> (-27.1899, -2.5589)
  line L5 (-22.3908, -9.5589) -> (-22.3908, -6.85)
  arc A1 centre (-24.6624, -4.5527) radius 1.9937 between (-22.6825, -4.3183) and (-24.7348, -2.5603)
  point P3 (-25.1899, -2.2146)
  point P6 (-27.1899, -2.5589)
  point P7 (-27.1899, -9.5589)
  dimension "d404" distance P3 P6 = 2
  dimension "d409" distance P6 P7 = 7
sketch "Sketch25" plane through (0, 0, -6.85) normal (0, 0, -1) x axis (1, 0, 0)
  curve K1 (-22.3111, 9.6073) -> (-11.8816, 21.5439)
  curve K2 (-22.3111, 9.6073) -> (-7.0917, -22.0832)
  line L1
  line L2
  line L3 (10.9929, -22.0832) -> (10.0999, -23)
  line L4
  curve K3 (7.0917, -22.0832) -> (22.3111, 9.6073)
  curve K4 (11.8816, 21.5439) -> (22.3111, 9.6073)
  line L5 (-20.16, -3.95) -> (-19.7081, -3.95)
  line L6 (-20.16, 3.95) -> (-20.16, -3.95)
  line L7 (-19.7081, 3.95) -> (-20.16, 3.95)
  line L8
  line L9 (10.1152, 22.5) -> (0, 0)
  line L10 (-7.6641, 22.5) -> (7.6641, 22.5)
  line L11 (10.0999, -23) -> (-10.0999, -23)
  closed curve K5 centre (9.882, 22.5)
  closed curve K6 centre (-9.882, 22.5)
  arc A1 centre (-2.1023, -18.9913) radius 1.7 clockwise from (-0.8, -20.0841) to (-3.612, -19.7728)
  arc A2 centre (0, 0) radius 20.1 clockwise from (-3.612, -19.7728) to (-19.7081, -3.95)
  arc A3 centre (0, 0) radius 20.1 clockwise from (-19.7081, 3.95) to (3.612, -19.7728)
  arc A4 centre (2.1023, -18.9913) radius 1.7 clockwise from (3.612, -19.7728) to (0.8, -20.0841)
  arc A5 centre (0, 0) radius 20.1 clockwise from (0.8, -20.0841) to (-0.8, -20.0841)
  closed curve K7 centre (10.1152, 22.5)
  closed curve K8 centre (-10.1152, 22.5)
  dimension "d406" angle L8 L9 = 47.479
revolve "Revolve5" sketch "Sketch24" AlongAngle 47.479
delete_face "DeleteFace5"
mirror "Mirror18"
delete_face "DeleteFace8"
fillet "Fillet22" radius 2
fillet "Fillet21" radius 1.2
